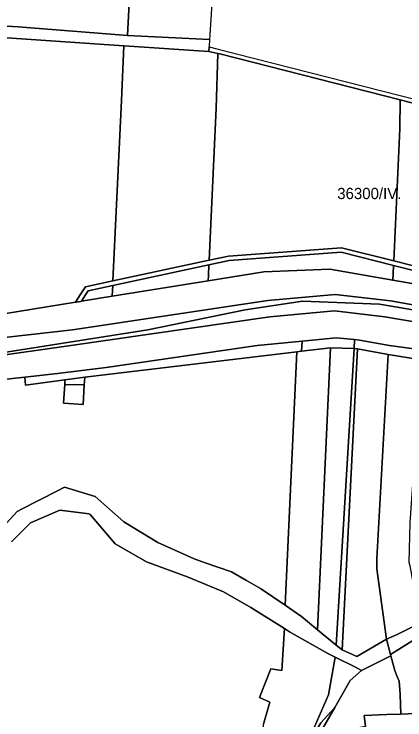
# Model space of a CAD drawing. Extents: x -545779 to -541342, y -1153413 to -1149956.
# Drawn here: x -544485 to -544310.7, y -1151065.6 to -1150751.1 of the extents above; entities that cross this region are included whole.
import ezdxf

# ---------------------------------------------------------------- set-up
doc = ezdxf.new("R2010")
doc.units = 0
for name, color, linetype in [('95560013', 7, 'Continuous'), ('95590013', 7, 'Continuous'), ('95630013', 7, 'Continuous'), ('95640013', 7, 'Continuous'), ('95660013', 7, 'Continuous')]:
    doc.layers.add(name, color=color, linetype=linetype)

msp = doc.modelspace()

# ---------------------------------------------------------------- linework, layer by layer
at = {"layer": '95560013'}
for points in [[(-544391.03, -1150663.52), (-544392.22, -1150674.11), (-544397.72, -1150760.42), (-544397.85, -1150762.48), (-544434.47, -1150760.63), (-544428.32, -1150642.67), (-544427.59, -1150640.66), (-544424.97, -1150642.23), (-544424.49, -1150642.52), (-544390.93, -1150662.63)], [(-544428.32, -1150642.67), (-544434.47, -1150760.63), (-544483.25, -1150756.77), (-544540.41, -1150753.5), (-544540.4, -1150753.33), (-544538.78, -1150719.82), (-544535.83, -1150659.11), (-544518.35, -1150656.44)], [(-544496.39, -1150783.2), (-544494.86, -1150761.21), (-544436.01, -1150765.31), (-544437.04, -1150789.64), (-544440.91, -1150870.01), (-544453.18, -1150872.64), (-544455.47, -1150876.18), (-544457.6, -1150879.49), (-544503.41, -1150886.87), (-544503.23, -1150884.2)], [(-544398.19, -1150767.72), (-544394.06, -1150768.61), (-544394.81, -1150793), (-544397.99, -1150860.82), (-544440.91, -1150870.01), (-544437.04, -1150789.64), (-544436.01, -1150765.31), (-544435.86, -1150765.32)], [(-544394.06, -1150768.61), (-544393.25, -1150768.78), (-544312.87, -1150789.37), (-544312.98, -1150802.25), (-544315.7, -1150861.08), (-544338.91, -1150855.23), (-544389.37, -1150858.98), (-544397.99, -1150860.82), (-544394.81, -1150793)], [(-544295.7, -1150793.77), (-544295.81, -1150806.53), (-544298.04, -1150865.53), (-544315.7, -1150861.08), (-544312.98, -1150802.25), (-544312.87, -1150789.37)], [(-544343.9, -1150899.85), (-544349.66, -1151025.46), (-544356.82, -1151019.59), (-544364.12, -1151014.56), (-544358.93, -1150901.63), (-544356.75, -1150901.37)], [(-544341.31, -1151032.3), (-544333.4, -1150900.17), (-544331.83, -1150900.22), (-544338.74, -1151034.41)]]:
    msp.add_lwpolyline(points, close=True, dxfattribs=at)
at = {"layer": '95590013'}
for points in [[(-544338.74, -1151034.41), (-544331.83, -1150900.22), (-544318.24, -1150902.75), (-544323.27, -1150993.64), (-544323.26, -1150998.27), (-544318.86, -1151029.7), (-544332.14, -1151037.33)], [(-544303.38, -1151022.3), (-544314.12, -1151027.52), (-544318.86, -1151029.7), (-544323.26, -1150998.27), (-544323.27, -1150993.64), (-544318.24, -1150902.75), (-544303.5, -1150905.18), (-544308.44, -1150977.82), (-544308.88, -1150995.29), (-544308.64, -1150996.44), (-544308.03, -1150999.33), (-544307.45, -1151002.7), (-544304.25, -1151021.22)]]:
    msp.add_lwpolyline(points, close=True, dxfattribs=at)
at = {"layer": '95630013'}
for points in [[(-544497.37, -1150896.16), (-544458.9, -1150891.75), (-544371.84, -1150878.72), (-544341.86, -1150876.04), (-544317.11, -1150878.83), (-544283.77, -1150884.86), (-544211.12, -1150898.96), (-544189.25, -1150902.17), (-544160.33, -1150906.42), (-544161.7, -1150910.69), (-544119.43, -1150926.78), (-544052.4, -1150968.07)], [(-544062.24, -1150968.12), (-544084.54, -1150954.05), (-544108.79, -1150937.82), (-544123.65, -1150929.34), (-544147.92, -1150918.16), (-544163.14, -1150915.17), (-544189.92, -1150909.92), (-544211.6, -1150905.59), (-544285.48, -1150891.85), (-544319.63, -1150885.97), (-544342.07, -1150883.41), (-544370.99, -1150885.95), (-544459.64, -1150898.72), (-544497.41, -1150904.1)]]:
    msp.add_lwpolyline(points, dxfattribs=at)
for points in [[(-544333.16, -1150896.18), (-544333.4, -1150900.17), (-544343.9, -1150899.85), (-544356.75, -1150901.37), (-544356.47, -1150896.82), (-544341.39, -1150895.37)], [(-544341.31, -1151032.3), (-544349.66, -1151025.46), (-544343.9, -1150899.85), (-544333.4, -1150900.17)], [(-544343.9, -1151112.02), (-544343.71, -1151129.28), (-544343.68, -1151131.77), (-544363.59, -1151120.98), (-544367.47, -1151101.32), (-544373.71, -1151080.64), (-544373.75, -1151067.46), (-544370.9, -1151057.68), (-544375.56, -1151055.72), (-544370.49, -1151042.82), (-544365.61, -1151043.58), (-544364.41, -1151024.94), (-544362.16, -1151026.34), (-544345.09, -1151036.02), (-544341.84, -1151037.65), (-544344.72, -1151054.48), (-544353.1, -1151073.42), (-544346.52, -1151094.49), (-544345.4, -1151109.2)], [(-544348.07, -1151070.69), (-544347.85, -1151071.82), (-544347.27, -1151076.35), (-544346, -1151082.21), (-544341.92, -1151089.17), (-544341.74, -1151093.07), (-544340.06, -1151129.45), (-544340.09, -1151132.86), (-544340.09, -1151133.08), (-544343.68, -1151131.77), (-544343.71, -1151129.28), (-544343.9, -1151112.02), (-544344.14, -1151090.54), (-544348.88, -1151081.19), (-544350.72, -1151075.23), (-544350.41, -1151070.68), (-544348.26, -1151067), (-544342.02, -1151060.09)]]:
    msp.add_lwpolyline(points, close=True, dxfattribs=at)
at = {"layer": '95640013'}
for points in [[(-544434.47, -1150760.63), (-544397.85, -1150762.48), (-544398.04, -1150765.38), (-544398.06, -1150765.72), (-544398.19, -1150767.72), (-544435.86, -1150765.32), (-544436.01, -1150765.31), (-544494.86, -1150761.21), (-544540.66, -1150758.74), (-544540.65, -1150758.49), (-544540.41, -1150753.5), (-544483.25, -1150756.77)], [(-544295.68, -1150791.73), (-544287.35, -1150793.85), (-544137.02, -1150832.04), (-544138.05, -1150835.38), (-544287.44, -1150795.88), (-544295.7, -1150793.77), (-544312.87, -1150789.37), (-544393.25, -1150768.78), (-544394.06, -1150768.61), (-544398.19, -1150767.72), (-544398.06, -1150765.72), (-544394, -1150766.75), (-544312.85, -1150787.37)], [(-544338.91, -1150855.23), (-544315.7, -1150861.08), (-544298.04, -1150865.53), (-544298.06, -1150866.03), (-544298.1, -1150867.08), (-544298.12, -1150867.58), (-544315.79, -1150863.12), (-544339.08, -1150857.24), (-544389.1, -1150860.97), (-544398.09, -1150862.89), (-544441.01, -1150872.08), (-544451.94, -1150874.42), (-544453.08, -1150876.18), (-544454.93, -1150879.06), (-544455.39, -1150879.13), (-544457.14, -1150879.42), (-544457.6, -1150879.49), (-544455.47, -1150876.18), (-544453.18, -1150872.64), (-544440.91, -1150870.01), (-544397.99, -1150860.82), (-544389.37, -1150858.98)], [(-544315.79, -1150863.12), (-544315.96, -1150866.8), (-544316.1, -1150869.68), (-544344.25, -1150864.77), (-544373.58, -1150865.95), (-544398.42, -1150869.95), (-544398.32, -1150867.54), (-544398.09, -1150862.89), (-544389.1, -1150860.97), (-544339.08, -1150857.24)], [(-544441.11, -1150874.29), (-544441.01, -1150872.08), (-544398.09, -1150862.89), (-544398.32, -1150867.54), (-544398.42, -1150869.95), (-544441.24, -1150876.85)], [(-544316.1, -1150869.68), (-544315.96, -1150866.8), (-544315.79, -1150863.12), (-544298.12, -1150867.58), (-544298.23, -1150870.34), (-544298.31, -1150872.77)], [(-544453.08, -1150876.18), (-544451.94, -1150874.42), (-544441.01, -1150872.08), (-544441.11, -1150874.29), (-544441.24, -1150876.85), (-544454.93, -1150879.06)], [(-544443.54, -1150911.65), (-544453.51, -1150912.96), (-544462.3, -1150914.11), (-544479.87, -1150916.42), (-544480.24, -1150912.9), (-544465.66, -1150911.27), (-544443.91, -1150908.54), (-544376.63, -1150898.77), (-544356.47, -1150896.82), (-544356.75, -1150901.37), (-544358.93, -1150901.63)], [(-544454.22, -1150916.38), (-544461.94, -1150916.1), (-544462.43, -1150916.09), (-544462.3, -1150914.11), (-544453.51, -1150912.96), (-544453.72, -1150916.42)], [(-544461.94, -1150916.1), (-544454.22, -1150916.38), (-544453.72, -1150916.42), (-544454.2, -1150925.15), (-544462.92, -1150924.5), (-544462.43, -1150916.09)], [(-544317.11, -1151036.5), (-544318.86, -1151029.7), (-544314.12, -1151027.52), (-544303.38, -1151022.3), (-544304.06, -1151028.26)], [(-544303.77, -1151030.34), (-544302.9, -1151034.58), (-544303.07, -1151042.8), (-544302.99, -1151054.57), (-544302.75, -1151062.65), (-544312.53, -1151063.09), (-544312.84, -1151054.25), (-544312.98, -1151052.2), (-544313.24, -1151048.34), (-544314.29, -1151045.96), (-544315.13, -1151043.69), (-544316.92, -1151037.05), (-544317.11, -1151036.5), (-544304.06, -1151028.26), (-544304.11, -1151028.68)], [(-544330.07, -1151043.55), (-544316.92, -1151037.05), (-544315.13, -1151043.69), (-544314.29, -1151045.96), (-544313.24, -1151048.34), (-544312.98, -1151052.2), (-544312.84, -1151054.25), (-544312.53, -1151063.09), (-544318.75, -1151063.23), (-544328.84, -1151063.72), (-544328.3, -1151068.58), (-544343.32, -1151071.22), (-544347.85, -1151071.82), (-544348.07, -1151070.69), (-544342.02, -1151060.09), (-544335.18, -1151048.11)], [(-544330.07, -1151043.55), (-544335.18, -1151048.11), (-544342.02, -1151060.09), (-544348.26, -1151067), (-544350.41, -1151070.68), (-544350.72, -1151075.23), (-544348.88, -1151081.19), (-544344.14, -1151090.54), (-544343.9, -1151112.02), (-544345.4, -1151109.2), (-544346.52, -1151094.49), (-544353.1, -1151073.42), (-544344.72, -1151054.48), (-544341.84, -1151037.65), (-544332.76, -1151042.2)]]:
    msp.add_lwpolyline(points, close=True, dxfattribs=at)
for points in [[(-544503.41, -1150886.87), (-544457.6, -1150879.49), (-544457.14, -1150879.42), (-544455.39, -1150879.13), (-544454.93, -1150879.06), (-544441.24, -1150876.85), (-544398.42, -1150869.95), (-544373.58, -1150865.95), (-544344.25, -1150864.77), (-544316.1, -1150869.68), (-544298.31, -1150872.77), (-544290.65, -1150874.11), (-544157.4, -1150897.33), (-544160.33, -1150906.42), (-544189.25, -1150902.17), (-544211.12, -1150898.96), (-544283.77, -1150884.86), (-544317.11, -1150878.83), (-544341.86, -1150876.04), (-544371.84, -1150878.72), (-544458.9, -1150891.75), (-544497.37, -1150896.16)], [(-544497.41, -1150904.1), (-544459.64, -1150898.72), (-544370.99, -1150885.95), (-544342.07, -1150883.41), (-544319.63, -1150885.97), (-544285.48, -1150891.85), (-544211.6, -1150905.59), (-544189.92, -1150909.92), (-544163.14, -1150915.17), (-544147.92, -1150918.16), (-544123.65, -1150929.34), (-544108.79, -1150937.82), (-544084.54, -1150954.05), (-544062.24, -1150968.12)], [(-544055.56, -1150984.77), (-544071.41, -1150976.11), (-544092.35, -1150963.53), (-544133.39, -1150937.74), (-544146.34, -1150931.13), (-544158.14, -1150927.27), (-544166.52, -1150925.65), (-544183.95, -1150922.29), (-544207.45, -1150917.93), (-544243.2, -1150911.81), (-544271.36, -1150907), (-544303.43, -1150900.67), (-544317.51, -1150898.82), (-544331.01, -1150896.39), (-544333.16, -1150896.18), (-544341.39, -1150895.37), (-544356.47, -1150896.82), (-544376.63, -1150898.77), (-544443.91, -1150908.54), (-544465.66, -1150911.27), (-544480.24, -1150912.9), (-544495.32, -1150914.58)], [(-544303.5, -1150905.18), (-544318.24, -1150902.75), (-544331.83, -1150900.22), (-544333.4, -1150900.17), (-544333.16, -1150896.18), (-544331.01, -1150896.39), (-544317.51, -1150898.82), (-544303.43, -1150900.67)], [(-544495.32, -1150914.58), (-544480.24, -1150912.9), (-544479.87, -1150916.42), (-544462.3, -1150914.11), (-544462.43, -1150916.09), (-544462.92, -1150924.5), (-544454.2, -1150925.15), (-544453.72, -1150916.42), (-544453.51, -1150912.96), (-544443.54, -1150911.65), (-544358.93, -1150901.63), (-544364.12, -1151014.56), (-544375.05, -1151007.02), (-544381.37, -1151003.47), (-544388.04, -1150999.72), (-544399.72, -1150995.64), (-544404.76, -1150993.88), (-544420.96, -1150986.53), (-544436.03, -1150977.33), (-544448.77, -1150966.14), (-544462.56, -1150961.91), (-544465.64, -1150963.49), (-544481.75, -1150971.78), (-544483.29, -1150972.57), (-544483.56, -1150972.71), (-544493.45, -1150983.24)], [(-544493.45, -1150983.24), (-544483.56, -1150972.71), (-544483.29, -1150972.57), (-544481.75, -1150971.78), (-544465.64, -1150963.49), (-544462.56, -1150961.91), (-544448.77, -1150966.14), (-544436.03, -1150977.33), (-544420.96, -1150986.53), (-544404.76, -1150993.88), (-544399.72, -1150995.64), (-544388.04, -1150999.72), (-544381.37, -1151003.47), (-544375.05, -1151007.02), (-544364.12, -1151014.56), (-544356.82, -1151019.59), (-544349.66, -1151025.46), (-544341.31, -1151032.3), (-544338.74, -1151034.41), (-544332.14, -1151037.33), (-544318.86, -1151029.7), (-544317.11, -1151036.5), (-544316.92, -1151037.05), (-544330.07, -1151043.55), (-544332.76, -1151042.2), (-544341.84, -1151037.65), (-544345.09, -1151036.02), (-544362.16, -1151026.34), (-544364.41, -1151024.94), (-544379.36, -1151015.61), (-544391.6, -1151008.56), (-544407.3, -1151002.07), (-544425.91, -1150995.14), (-544439.85, -1150987.13), (-544451.13, -1150974.1), (-544451.31, -1150973.89), (-544451.49, -1150973.87), (-544464.59, -1150972.15), (-544477.68, -1150977.83), (-544486.23, -1150986.27)], [(-544486.23, -1150986.27), (-544477.68, -1150977.83), (-544464.59, -1150972.15), (-544451.49, -1150973.87), (-544451.31, -1150973.89), (-544451.13, -1150974.1), (-544439.85, -1150987.13), (-544425.91, -1150995.14), (-544407.3, -1151002.07), (-544391.6, -1151008.56), (-544379.36, -1151015.61), (-544364.41, -1151024.94), (-544365.61, -1151043.58), (-544370.49, -1151042.82), (-544375.56, -1151055.72), (-544370.9, -1151057.68), (-544373.75, -1151067.46)], [(-544328.3, -1151068.58), (-544328.84, -1151063.72), (-544318.75, -1151063.23), (-544312.53, -1151063.09), (-544302.75, -1151062.65)]]:
    msp.add_lwpolyline(points, dxfattribs=at)
at = {"layer": '95660013'}
for points in [[(-544392.22, -1150674.11), (-544397.72, -1150760.42), (-544397.85, -1150762.48), (-544398.04, -1150765.38), (-544398.06, -1150765.72), (-544394, -1150766.75), (-544312.85, -1150787.37), (-544295.68, -1150791.73), (-544287.35, -1150793.85), (-544137.02, -1150832.04), (-544138.05, -1150835.38), (-544138.43, -1150836.61), (-544154.97, -1150890.12), (-544155.31, -1150891.22), (-544155.87, -1150893.02), (-544156.18, -1150894.03), (-544156.62, -1150895.12), (-544156.98, -1150896.02), (-544157.4, -1150897.33), (-544160.33, -1150906.42), (-544161.7, -1150910.69), (-544119.43, -1150926.78), (-544052.4, -1150968.07)], [(-544490.395, -1150902.035), (-544425.322, -1150891.827), (-544381.939, -1150882.895), (-544356.419, -1150879.067), (-544321.969, -1150880.343), (-544269.653, -1150889.275), (-544213.511, -1150902.035), (-544168.853, -1150916.07), (-544131.849, -1150926.278), (-544079.535, -1150951.797), (-544079.025, -1150952.149), (-544042.531, -1150977.317)], [(-544042.531, -1150977.317), (-544079.025, -1150952.149), (-544079.535, -1150951.797), (-544131.849, -1150926.278), (-544168.853, -1150916.07), (-544213.511, -1150902.035), (-544269.653, -1150889.275), (-544321.969, -1150880.343), (-544356.419, -1150879.067), (-544381.939, -1150882.895), (-544425.322, -1150891.827), (-544490.395, -1150902.035)]]:
    msp.add_lwpolyline(points, dxfattribs=at)

# ---------------------------------------------------------------- texts
msp.add_text('36300/IV.', height=5, rotation=360, dxfattribs=at).set_placement((-544340.885, -1150833.55))

doc.saveas('drawing.dxf')
